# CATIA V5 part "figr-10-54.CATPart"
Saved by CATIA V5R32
Part number: Part1
Bounding box of the stored display mesh (mm): x 0 to 100, y -43.492 to 31.433, z -3.653 to 11.537
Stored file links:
  D:\PROJECTS\Project 2022\CATIA V5 6R 2022\Resources\Part Files\c10_catia_v5_6r2022_prt\c10_catia_v5_6r2022_prt\figr-10-54.CATPart
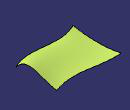
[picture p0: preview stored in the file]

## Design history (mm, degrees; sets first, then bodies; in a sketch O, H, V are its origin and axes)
Set1
  Sketch1 on yz-plane, origin (0, 0, 0), H (0, 1, 0), V (0, 0, 1)
  Plane1: type Offset, RefPlane yz-plane, Offset 100
  Sketch2 on xy-plane, origin (0, 0, 0), H (1, 0, 0), V (0, 1, 0)
    spline S1 through (0, 31.0443) (19.7053, 31.0443) (51.809, 26.4574) (100, 31.0443)
    reference intersected line E1 through (100, 0) direction (0, 1) from Plane1
    point P1 (0, 31.0443)
    point P2 (100, 31.0443)
    coincidence: P1 V, P2 E1
  Sketch3 on xy-plane, origin (0, 0, 0), H (1, 0, 0), V (0, 1, 0)
    spline S1 through (0, -43.492) (26.209, -36.2295) (80.3728, -38.1407) (100, -32.0249)
    reference intersected line E1 through (100, 0) direction (0, 1) from Plane1
    point P1 (0, -43.492)
    point P2 (100, -32.0249)
    coincidence: P1 V, P2 E1
  Sketch4 on Plane1, origin (100, 0, 0), H (0, 1, 0), V (0, 0, 1)
    spline S1 through (-32.0249, 0) (-14.5305, 11.3827) (11.9668, 5.3652) (31.0443, 0)
    reference projected point E1 (31.0443, 0) from vertex of Sketch2
    reference projected point E2 (-32.0249, 0) from vertex of Sketch3
    point P1 (-32.0249, 0)
    point P2 (31.0443, 0)
    coincidence: P1 H, P2 H, P2 E1, P1 E2
  Sketch5 on yz-plane, origin (0, 0, 0), H (0, 1, 0), V (0, 0, 1)
    spline S1 through (31.0443, 0) (7.4727, -3.1675) (-43.492, 0)
    reference projected point E1 (-43.492, 0) from vertex of Sketch3
    reference projected point E2 (31.0443, 0) from vertex of Sketch2
    point P1 (31.0443, 0)
    point P2 (-43.492, 0)
    coincidence: P1 H, P2 H, P2 E1, P1 E2
  Fill1: Boundary (Sketch5; Sketch3; Sketch4; Sketch2)
Body1 (main body)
